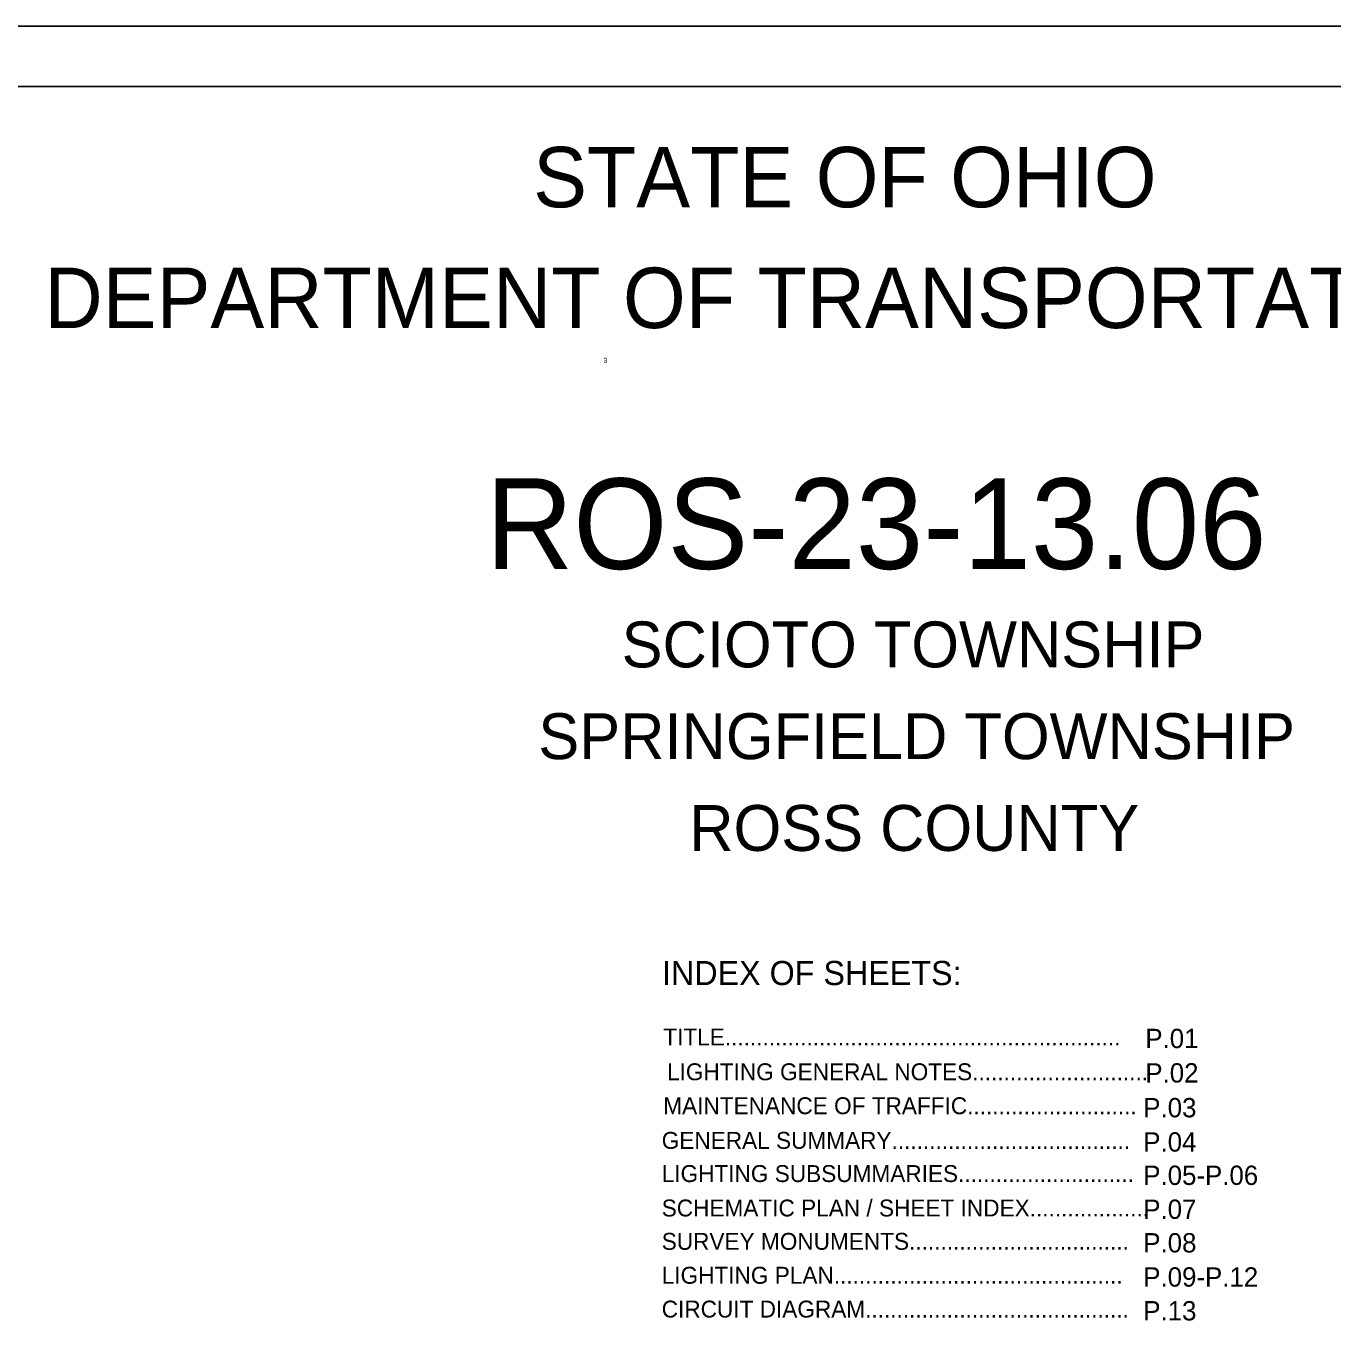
# Model space of a CAD drawing. Extents: x 0 to 51, y -1.2 to 22.
# Drawn here: x 9.77 to 20.59, y 11.17 to 22 of the extents above; entities that cross this region are included whole.
import ezdxf

# ---------------------------------------------------------------- set-up
doc = ezdxf.new("R2010")
doc.units = 0
for name, color, linetype in [('GM_X_Section_Text', 7, 'Continuous'), ('SH_Border', 7, 'Continuous'), ('SH_Cut_Line', 7, 'Continuous'), ('SH_Data', 7, 'Continuous'), ('SH_Text', 7, 'Continuous')]:
    doc.layers.add(name, color=color, linetype=linetype)

msp = doc.modelspace()

# ---------------------------------------------------------------- linework, layer by layer
at = {"layer": 'SH_Border'}
msp.add_lwpolyline([(1.5, 21.5), (33.5, 21.5), (33.5, 0.5), (1.5, 0.5)], close=True, dxfattribs=at)
at = {"layer": 'SH_Cut_Line'}
msp.add_lwpolyline([(0, 0), (34, 0), (34, 22), (0, 22)], close=True, dxfattribs=at)

# ---------------------------------------------------------------- texts
at = {"layer": 'GM_X_Section_Text'}
msp.add_text('3', height=0.0419, rotation=0, dxfattribs=at).set_placement((14.55, 19.212))
at = {"layer": 'SH_Data'}
for s, height, p in [('INDEX OF SHEETS:', 0.2, (15.035, 14.059)), ('TITLE...............................................................', 0.14, (15.046, 13.559)), ('P.01', 0.16, (19.039, 13.537)), ('LIGHTING GENERAL NOTES............................', 0.14, (15.077, 13.271)), ('P.02', 0.16, (19.039, 13.252)), ('MAINTENANCE OF TRAFFIC...........................', 0.14, (15.046, 12.99)), ('P.03', 0.16, (19.022, 12.964)), ('GENERAL SUMMARY......................................', 0.14, (15.033, 12.703)), ('P.04', 0.16, (19.022, 12.68)), ('LIGHTING SUBSUMMARIES............................', 0.14, (15.033, 12.428)), ('P.05-P.06', 0.16, (19.022, 12.404)), ('SCHEMATIC PLAN / SHEET INDEX...................', 0.14, (15.033, 12.143)), ('P.07', 0.16, (19.022, 12.123)), ('SURVEY MONUMENTS...................................', 0.14, (15.033, 11.867)), ('P.08', 0.16, (19.022, 11.845)), ('LIGHTING PLAN..............................................', 0.14, (15.033, 11.586)), ('P.09-P.12', 0.16, (19.022, 11.562)), ('CIRCUIT DIAGRAM..........................................', 0.14, (15.033, 11.306)), ('P.13', 0.16, (19.022, 11.282))]:
    msp.add_text(s, height=height, dxfattribs=at).set_placement(p)
at = {"layer": 'SH_Text'}
for s, height, p in [('STATE OF OHIO', 0.5, (13.968, 20.5)), ('DEPARTMENT OF TRANSPORTATION', 0.5, (9.92, 19.5)), ('ROS-23-13.06', 0.75, (13.576, 17.505)), ('SCIOTO TOWNSHIP', 0.38, (14.701, 16.69)), ('SPRINGFIELD TOWNSHIP', 0.38, (14.011, 15.93)), ('ROSS COUNTY', 0.38, (15.261, 15.17))]:
    msp.add_text(s, height=height, dxfattribs=at).set_placement(p)

doc.saveas('drawing.dxf')
